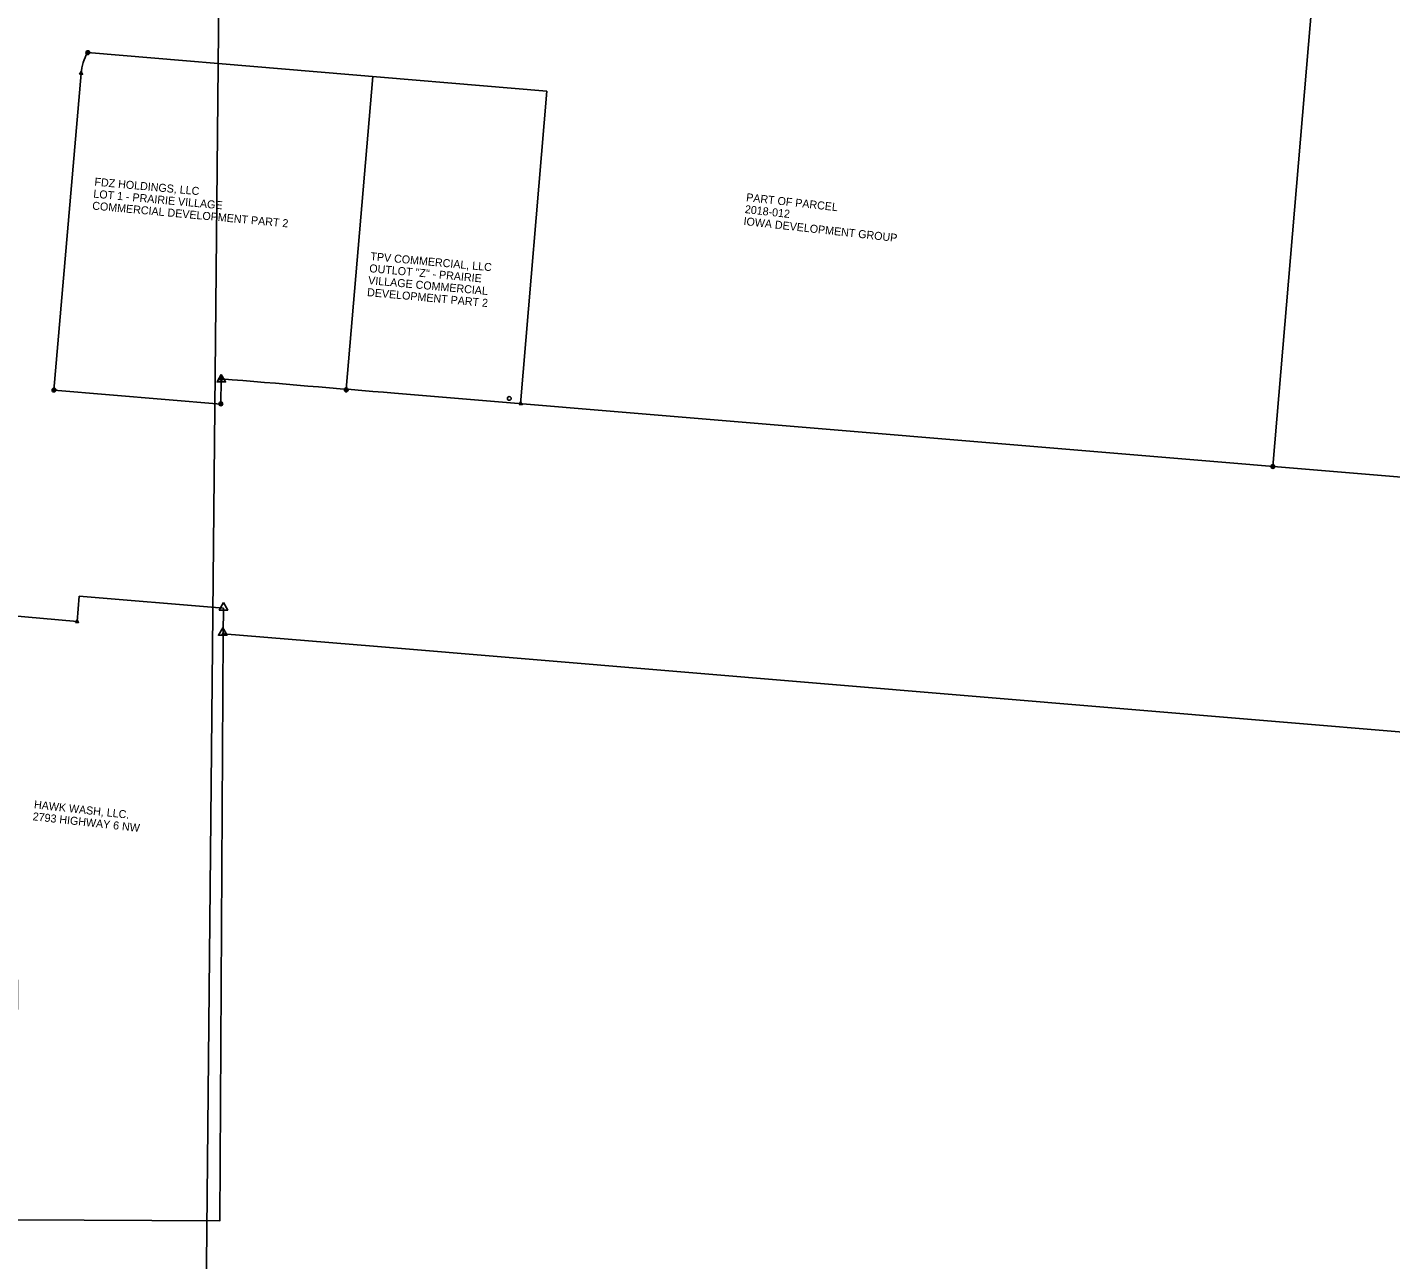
# Model space of a CAD drawing. Extents: x 20500076 to 20505422, y 7951999 to 7957351.
# Drawn here: x 20502582 to 20503387, y 7953367 to 7954095 of the extents above; entities that cross this region are included whole.
import ezdxf

# ---------------------------------------------------------------- set-up
doc = ezdxf.new("R2010")
doc.units = 0
for name, color, linetype in [('DisROW Existing', 7, 'Continuous'), ('DisROW Property Lines', 7, 'Continuous'), ('rowdsnSymbolsProposed', 7, 'Continuous'), ('Section Lines', 7, 'Continuous'), ('SurControl', 7, 'Continuous'), ('SurSectionCorner', 7, 'Continuous'), ('Text', 7, 'Continuous')]:
    doc.layers.add(name, color=color, linetype=linetype)

msp = doc.modelspace()

# ---------------------------------------------------------------- linework, layer by layer
at = {"layer": 'DisROW Existing'}
for p, q in [((20502598.22, 7953880.54), (20502614.23, 7954067.54)), ((20502696.97, 7953887.24), (20502696.7, 7953872.21)), ((20502598.22, 7953880.54), (20502696.7, 7953872.21)), ((20502799.23, 7953878.73), (20504435.69, 7953742.18))]:
    msp.add_line(p, q, dxfattribs=at)
for points in [[(20501779.83, 7953818.16), (20502611.84, 7953743.9), (20502613.1, 7953758.85)], [(20502613.1, 7953758.85), (20502698.31, 7953751.7), (20502698.22, 7953736.7), (20502786.89, 7953729.24), (20503932.03, 7953633.68)]]:
    msp.add_lwpolyline(points, dxfattribs=at)
for centre, radius, start, end in [((20502644.13, 7954064.99), 30, 150.15408, 175.12204), ((20508853.82, 8027226.31), 73597.05, 265.2012455, 265.2811368)]:
    msp.add_arc(centre, radius, start, end, dxfattribs=at)
at = {"layer": 'DisROW Property Lines'}
for p, q in [((20502889.27, 7954057.13), (20502618.1, 7954079.92)), ((20502770.7, 7953881.09), (20502786.51, 7954065.76)), ((20502873.75, 7953872.51), (20502889.27, 7954057.13))]:
    msp.add_line(p, q, dxfattribs=at)
for points in [[(20503317.82, 7953835.45), (20503374.94, 7954511), (20502721.83, 7954566.23)], [(20502698.22, 7953736.42), (20502696.14, 7953389.92), (20502575.86, 7953390.64), (20502576.71, 7953532.3)]]:
    msp.add_lwpolyline(points, dxfattribs=at)
at = {"layer": 'rowdsnSymbolsProposed'}
for points in [[(20502618.1, 7954079.92), (20502618.11, 7954079.92)], [(20502614.24, 7954067.56), (20502614.24, 7954067.56)], [(20502696.97, 7953887.24), (20502696.97, 7953887.24)], [(20502598.22, 7953880.54), (20502598.22, 7953880.55)], [(20502770.7, 7953881.09), (20502770.7, 7953881.09)], [(20502696.7, 7953872.21), (20502696.7, 7953872.21)], [(20502873.75, 7953872.51), (20502873.75, 7953872.51)], [(20503317.82, 7953835.45), (20503317.82, 7953835.46)], [(20503318.94, 7953835.36), (20503318.94, 7953835.36)]]:
    msp.add_lwpolyline(points, dxfattribs=at)
at = {"layer": 'Section Lines'}
msp.add_lwpolyline([(20502738.54, 7957350.88), (20502701.64, 7955344.89), (20502701.11, 7954679.24), (20502675.39, 7952029.46)], dxfattribs=at)
at = {"layer": 'SurControl'}
for points in [[(20502697.04, 7953889.8), (20502699.59, 7953885.39), (20502694.49, 7953885.39)], [(20502698.33, 7953755.08), (20502700.88, 7953750.67), (20502695.78, 7953750.67)], [(20502697.87, 7953740.21), (20502700.42, 7953735.8), (20502695.32, 7953735.8)]]:
    msp.add_lwpolyline(points, close=True, dxfattribs=at)
for centre in [(20502618.22, 7954079.85), (20502598.22, 7953880.58), (20502770.79, 7953880.64), (20502696.78, 7953872.47), (20502867.04, 7953875.64), (20503317.82, 7953835.47)]:
    msp.add_circle(centre, 1.12, dxfattribs=at)
at = {"layer": 'SurSectionCorner'}
for points in [[(20502617.19, 7954079.39), (20502619.02, 7954079.39), (20502618.1, 7954080.97)], [(20502613.32, 7954067.03), (20502615.15, 7954067.03), (20502614.24, 7954068.61)], [(20502696.05, 7953886.71), (20502697.88, 7953886.71), (20502696.97, 7953888.3)], [(20502597.3, 7953880.02), (20502599.13, 7953880.02), (20502598.22, 7953881.6)], [(20502769.78, 7953880.56), (20502771.61, 7953880.56), (20502770.7, 7953882.14)], [(20502695.78, 7953871.68), (20502697.61, 7953871.68), (20502696.7, 7953873.27)], [(20502872.84, 7953871.98), (20502874.66, 7953871.98), (20502873.75, 7953873.56)], [(20503316.91, 7953834.93), (20503318.74, 7953834.93), (20503317.82, 7953836.51)], [(20502610.93, 7953743.38), (20502612.76, 7953743.38), (20502611.84, 7953744.96)], [(20502697.3, 7953735.9), (20502699.13, 7953735.9), (20502698.22, 7953737.48)]]:
    msp.add_lwpolyline(points, close=True, dxfattribs=at)

# ---------------------------------------------------------------- texts
at = {"layer": 'Text'}
for s, height, rotation, p in [('FDZ HOLDINGS, LLC', 4.7244, 354.76449, (20502621.97, 7954001.32)), ('COMMERCIAL DEVELOPMENT PART 2', 4.7244, 354.76449, (20502620.68, 7953987.21)), ('LOT 1 - PRAIRIE VILLAGE', 4.7244, 354.76449, (20502621.32, 7953994.26)), ('PART OF PARCEL', 4.7244, 353.65909, (20503006.72, 7953992.17)), ('2018-012', 4.724, 353.65909, (20503005.94, 7953985.13)), ('IOWA DEVELOPMENT GROUP', 4.7244, 353.65909, (20503005.16, 7953978.09)), ('TPV COMMERCIAL, LLC', 4.7244, 354.76449, (20502784.88, 7953957.29)), ('OUTLOT "Z" - PRAIRIE ', 4.7244, 354.76449, (20502784.23, 7953950.23)), ('VILLAGE COMMERCIAL ', 4.7244, 354.76449, (20502783.58, 7953943.17)), ('DEVELOPMENT PART 2', 4.7244, 354.76449, (20502782.94, 7953936.11)), ('HAWK WASH, LLC.', 4.7244, 353.70825, (20502586.27, 7953633.6)), ('2793 HIGHWAY 6 NW', 4.7244, 353.70825, (20502585.49, 7953626.56))]:
    msp.add_text(s, height=height, rotation=rotation, dxfattribs=at).set_placement(p)

doc.saveas('drawing.dxf')
